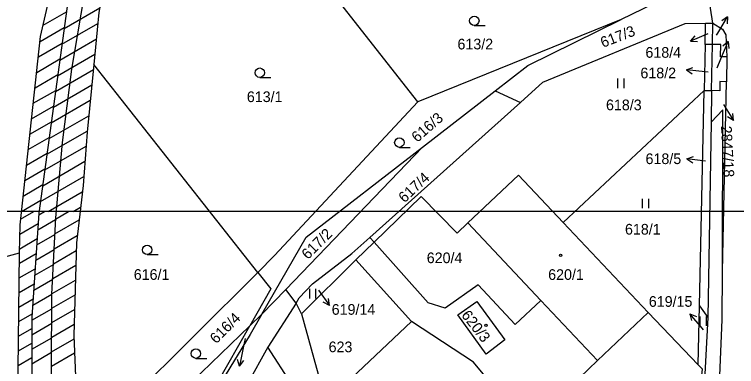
# Model space of a CAD drawing. Extents: x -558500 to -557517, y -1073973 to -1073051.
# Drawn here: x -558299.9 to -558184.7, y -1073724.7 to -1073668.6 of the extents above; entities that cross this region are included whole.
import ezdxf

# ---------------------------------------------------------------- set-up
doc = ezdxf.new("R2010")
doc.units = 0
for name, color, linetype in [('Default', 7, 'Continuous'), ('Hranice parcel', 7, 'Continuous'), ('Kolej', 7, 'Continuous'), ('Parcelní čísla', 7, 'Continuous'), ('Pop  PČ popisy', 7, 'Continuous'), ('Svazek obcí údolí Desné', 7, 'Continuous'), ('Značky budov', 7, 'Continuous'), ('Značky kultur', 7, 'Continuous')]:
    doc.layers.add(name, color=color, linetype=linetype)

msp = doc.modelspace()

# ---------------------------------------------------------------- linework, layer by layer
at = {"layer": 'Default'}
msp.add_lwpolyline([(-557909.21, -1073700), (-558500, -1073700), (-558500, -1073200), (-557800, -1073200), (-557800, -1073567.6)], dxfattribs=at)
at = {"layer": 'Hranice parcel'}
for p, q in [((-558235.56, -1073682.51), (-558250.61, -1073663.38)), ((-558188.53, -1073669.97), (-558189.35, -1073664.58)), ((-558196.23, -1073665.95), (-558203.14, -1073669.36)), ((-558203.14, -1073669.36), (-558235.56, -1073682.51)), ((-558189.77, -1073673.37), (-558189.69, -1073669.98)), ((-558189.69, -1073669.98), (-558188.53, -1073669.97)), ((-558188.59, -1073673.36), (-558188.53, -1073669.97)), ((-558188.53, -1073669.97), (-558186.98, -1073670.93)), ((-558189.77, -1073673.37), (-558189.93, -1073680.69)), ((-558188.59, -1073673.36), (-558189.77, -1073673.37)), ((-558188.72, -1073680.72), (-558188.59, -1073673.36)), ((-558187.23, -1073673.34), (-558188.59, -1073673.36)), ((-558186.31, -1073675.34), (-558186.36, -1073679.31)), ((-558261.12, -1073709.7), (-558287.25, -1073676.53)), ((-558187.01, -1073709.55), (-558186.36, -1073679.31)), ((-558234.84, -1073689.73), (-558223.26, -1073680.77)), ((-558223.26, -1073680.77), (-558219.23, -1073682.6)), ((-558189.93, -1073680.69), (-558212.4, -1073701.75)), ((-558190.64, -1073715.05), (-558189.93, -1073680.69)), ((-558189.93, -1073680.69), (-558188.72, -1073680.72)), ((-558188.72, -1073680.72), (-558188.81, -1073685.75)), ((-558187.4, -1073680.75), (-558188.72, -1073680.72)), ((-558243.24, -1073704.13), (-558219.23, -1073682.6)), ((-558186.92, -1073683.79), (-558188.81, -1073685.75)), ((-558187.01, -1073709.55), (-558186.92, -1073683.79)), ((-558188.81, -1073685.75), (-558189.35, -1073716.89)), ((-558256.63, -1073712.41), (-558234.84, -1073689.73)), ((-558227.63, -1073701.8), (-558215.96, -1073714.16)), ((-558212.4, -1073701.75), (-558198.87, -1073716.11)), ((-558242.57, -1073704.88), (-558243.24, -1073704.13)), ((-558245.46, -1073707.69), (-558242.57, -1073704.88)), ((-558233.91, -1073714.56), (-558242.57, -1073704.88)), ((-558339.57, -1073717.56), (-558299.09, -1073706.57)), ((-558245.46, -1073707.69), (-558254.11, -1073716.3)), ((-558236.6, -1073717.53), (-558245.46, -1073707.69)), ((-558256.63, -1073712.41), (-558260.45, -1073716.38)), ((-558255.01, -1073714.6), (-558256.63, -1073712.41)), ((-558255.01, -1073714.6), (-558259.48, -1073721.62)), ((-558254.11, -1073716.3), (-558255.01, -1073714.6)), ((-558206.91, -1073723.76), (-558215.96, -1073714.16)), ((-558190.86, -1073724.46), (-558190.64, -1073715.05)), ((-558190.64, -1073715.05), (-558189.35, -1073716.89)), ((-558262.39, -1073718.25), (-558260.45, -1073716.38)), ((-558254.11, -1073716.3), (-558250.26, -1073730.4)), ((-558198.87, -1073716.11), (-558206.91, -1073723.76)), ((-558190.86, -1073724.46), (-558198.87, -1073716.11)), ((-558250.26, -1073730.4), (-558236.6, -1073717.53)), ((-558226.69, -1073724.03), (-558236.6, -1073717.53)), ((-558274.72, -1073739.9), (-558262.39, -1073718.25)), ((-558259.48, -1073721.62), (-558281.15, -1073760.49)), ((-558241.29, -1073750.06), (-558259.48, -1073721.62)), ((-558218.17, -1073734.19), (-558226.69, -1073724.03))]:
    msp.add_line(p, q, dxfattribs=at)
for points in [[(-558223.26, -1073680.77), (-558218.03, -1073676.72), (-558203.14, -1073669.36)], [(-558219.23, -1073682.6), (-558215.65, -1073679.39), (-558192.95, -1073670.01), (-558189.69, -1073669.98)], [(-558186.98, -1073670.93), (-558186.43, -1073671.79), (-558186.31, -1073675.34)], [(-558186.31, -1073675.34), (-558187.29, -1073675.33), (-558187.23, -1073673.34)], [(-558186.36, -1073679.31), (-558187.4, -1073679.28), (-558187.4, -1073680.75)], [(-558235.56, -1073682.51), (-558258.46, -1073707.03), (-558261.12, -1073709.7)], [(-558260.45, -1073716.38), (-558253.37, -1073704.07), (-558234.84, -1073689.73)], [(-558227.63, -1073701.8), (-558219.54, -1073694.18), (-558212.4, -1073701.75)], [(-558242.57, -1073704.88), (-558235.04, -1073697.59), (-558229.33, -1073703.46), (-558227.63, -1073701.8)], [(-558255.01, -1073714.6), (-558254.51, -1073713.78), (-558252.39, -1073711.53), (-558246.1, -1073706.69), (-558243.24, -1073704.13)], [(-558289.37, -1073741.07), (-558281.4, -1073729.91), (-558261.12, -1073709.7)], [(-558261.12, -1073709.7), (-558259.03, -1073712.35), (-558262.39, -1073718.25)], [(-558188.37, -1073749.08), (-558187.04, -1073717.25), (-558187.01, -1073709.55)], [(-558215.96, -1073714.16), (-558220.05, -1073717.99), (-558225.94, -1073711.71), (-558231.23, -1073715.41), (-558233.91, -1073714.56)], [(-558224.7, -1073722.72), (-558229.2, -1073716.48), (-558226.19, -1073714.33), (-558221.69, -1073720.48), (-558224.7, -1073722.72)], [(-558260.45, -1073716.38), (-558262.32, -1073719.63), (-558274.72, -1073739.9)], [(-558189.35, -1073716.89), (-558191.03, -1073748.95), (-558192.59, -1073755.8)], [(-558262.39, -1073718.25), (-558277.79, -1073733.11), (-558288.61, -1073748.35)], [(-558200.5, -1073781.61), (-558202.2, -1073784.23), (-558205.35, -1073784.79), (-558212.68, -1073729.29), (-558206.91, -1073723.76)], [(-558191.18, -1073734.38), (-558190.17, -1073725.16), (-558190.86, -1073724.46)]]:
    msp.add_lwpolyline(points, dxfattribs=at)
at = {"layer": 'Kolej'}
msp.add_lwpolyline([(-558287.36, -1073784.19), (-558289.56, -1073772.87), (-558290.66, -1073766.21), (-558291.24, -1073762.21), (-558292.77, -1073749.06), (-558293.62, -1073737.47), (-558294.02, -1073725.05), (-558293.93, -1073713.18), (-558293.34, -1073701.02), (-558292.27, -1073689.01), (-558290.77, -1073677.31), (-558288.8, -1073665.65)], dxfattribs=at)
at = {"layer": 'Pop  PČ popisy'}
for p, q in [((-558187.72, -1073671.53), (-558186.17, -1073668.96)), ((-558186.17, -1073668.96), (-558187.12, -1073669.56)), ((-558186.17, -1073668.96), (-558186.26, -1073670.07)), ((-558189.32, -1073671.65), (-558192.08, -1073672.82)), ((-558192.08, -1073672.82), (-558191.36, -1073671.97)), ((-558187.93, -1073671.89), (-558187.72, -1073671.53)), ((-558192.08, -1073672.82), (-558190.96, -1073672.89)), ((-558187.24, -1073675.66), (-558186.07, -1073672.9)), ((-558186.07, -1073672.9), (-558186.92, -1073673.62)), ((-558186.07, -1073672.9), (-558186, -1073674.02)), ((-558187.86, -1073677.09), (-558187.24, -1073675.66)), ((-558192.74, -1073677.42), (-558191.7, -1073677.02)), ((-558189.76, -1073677.73), (-558192.74, -1073677.42)), ((-558192.74, -1073677.42), (-558191.8, -1073678.02)), ((-558189.29, -1073677.78), (-558189.76, -1073677.73)), ((-558186.84, -1073682.95), (-558185.25, -1073685.5)), ((-558185.25, -1073685.5), (-558185.36, -1073684.38)), ((-558185.25, -1073685.5), (-558186.2, -1073684.91)), ((-558192.66, -1073691.6), (-558191.6, -1073691.23)), ((-558189.68, -1073691.97), (-558192.66, -1073691.6)), ((-558192.66, -1073691.6), (-558191.73, -1073692.22)), ((-558251.41, -1073712.52), (-558249.69, -1073714.98)), ((-558249.69, -1073714.98), (-558250.67, -1073714.45)), ((-558249.69, -1073714.98), (-558249.85, -1073713.87)), ((-558190.25, -1073718.6), (-558192.18, -1073716.3)), ((-558192.18, -1073716.3), (-558191.15, -1073716.75)), ((-558192.18, -1073716.3), (-558191.92, -1073717.39)), ((-558190.03, -1073718.86), (-558190.25, -1073718.6)), ((-558263.11, -1073720.25), (-558263.42, -1073721.72)), ((-558263.42, -1073721.72), (-558264.04, -1073724.66)), ((-558264.04, -1073724.66), (-558264.33, -1073723.57)), ((-558264.04, -1073724.66), (-558263.35, -1073723.78))]:
    msp.add_line(p, q, dxfattribs=at)
at = {"layer": 'Svazek obcí údolí Desné'}
for p, q in [((-558295.33, -1073670.27), (-558291.64, -1073668.14)), ((-558292, -1073670.82), (-558286.3, -1073667.52)), ((-558295.83, -1073672.87), (-558291.98, -1073670.64)), ((-558292.34, -1073673.32), (-558286.61, -1073670.01)), ((-558296.1, -1073675.33), (-558292.32, -1073673.15)), ((-558292.68, -1073675.83), (-558286.85, -1073672.46)), ((-558293.03, -1073678.33), (-558287.09, -1073674.91)), ((-558296.37, -1073677.8), (-558292.66, -1073675.66)), ((-558293.37, -1073680.84), (-558287.33, -1073677.36)), ((-558296.64, -1073680.26), (-558293, -1073678.16)), ((-558293.71, -1073683.35), (-558287.58, -1073679.81)), ((-558296.91, -1073682.73), (-558293.34, -1073680.67)), ((-558294.05, -1073685.85), (-558287.82, -1073682.26)), ((-558297.18, -1073685.19), (-558293.68, -1073683.18)), ((-558297.45, -1073687.66), (-558294.02, -1073685.68)), ((-558294.39, -1073688.36), (-558288.07, -1073684.71)), ((-558294.73, -1073690.86), (-558288.31, -1073687.16)), ((-558297.72, -1073690.12), (-558294.37, -1073688.19)), ((-558295.07, -1073693.37), (-558288.5, -1073689.58)), ((-558297.99, -1073692.59), (-558294.71, -1073690.69)), ((-558295.41, -1073695.88), (-558288.69, -1073691.99)), ((-558298.26, -1073695.05), (-558295.05, -1073693.2)), ((-558295.75, -1073698.38), (-558288.87, -1073694.41)), ((-558298.53, -1073697.52), (-558295.39, -1073695.71)), ((-558294.55, -1073700), (-558289.1, -1073696.85)), ((-558298.8, -1073699.98), (-558295.73, -1073698.21)), ((-558290.55, -1073700), (-558289.38, -1073699.32)), ((-558298.93, -1073701.22), (-558296.82, -1073700)), ((-558296.03, -1073700.52), (-558295.12, -1073700)), ((-558293.35, -1073701.19), (-558291.29, -1073700)), ((-558299.05, -1073703.6), (-558296.12, -1073701.91)), ((-558296.19, -1073702.93), (-558293.36, -1073701.29)), ((-558293.47, -1073703.57), (-558289.61, -1073701.34)), ((-558296.35, -1073705.33), (-558293.47, -1073703.67)), ((-558293.58, -1073705.94), (-558289.89, -1073703.81)), ((-558299.08, -1073705.93), (-558296.28, -1073704.31)), ((-558296.51, -1073707.73), (-558293.59, -1073706.04)), ((-558293.7, -1073708.32), (-558290.06, -1073706.22)), ((-558299.11, -1073708.25), (-558296.45, -1073706.71)), ((-558296.68, -1073710.14), (-558293.7, -1073708.42)), ((-558293.81, -1073710.69), (-558290.13, -1073708.57)), ((-558299.14, -1073710.58), (-558296.61, -1073709.12)), ((-558296.84, -1073712.54), (-558293.81, -1073710.79)), ((-558293.92, -1073713.07), (-558290.19, -1073710.92)), ((-558299.17, -1073712.91), (-558296.77, -1073711.52)), ((-558297, -1073714.94), (-558293.93, -1073713.17)), ((-558293.95, -1073715.39), (-558290.26, -1073713.26)), ((-558299.2, -1073715.23), (-558296.93, -1073713.92)), ((-558297.13, -1073717.33), (-558293.95, -1073715.49)), ((-558293.97, -1073717.71), (-558290.33, -1073715.61)), ((-558299.23, -1073717.56), (-558297.1, -1073716.33)), ((-558297.14, -1073719.64), (-558293.97, -1073717.81)), ((-558293.98, -1073720.03), (-558290.39, -1073717.96)), ((-558299.26, -1073719.88), (-558297.13, -1073718.66)), ((-558297.14, -1073721.95), (-558293.98, -1073720.13)), ((-558294, -1073722.35), (-558290.42, -1073720.28)), ((-558299.29, -1073722.21), (-558297.14, -1073720.97)), ((-558297.14, -1073724.26), (-558294, -1073722.45)), ((-558294.02, -1073724.67), (-558290.33, -1073722.54)), ((-558299.31, -1073724.54), (-558297.14, -1073723.28))]:
    msp.add_line(p, q, dxfattribs=at)
for points in [[(-558237.23, -1073540.41), (-558250.35, -1073559.71), (-558264.4, -1073584.99), (-558277.08, -1073613.49), (-558283.33, -1073632.3), (-558290.3, -1073658.29), (-558296.01, -1073700.28), (-558297.13, -1073716.84), (-558297.21, -1073758.56)], [(-558299.09, -1073706.57), (-558299.03, -1073702.13), (-558295.75, -1073672.1), (-558286.79, -1073633.11)], [(-558281.64, -1073647.46), (-558284.84, -1073659.61), (-558286.44, -1073668.26), (-558287.25, -1073676.53)], [(-558287.25, -1073676.53), (-558288.33, -1073687.34), (-558288.98, -1073695.83), (-558290.03, -1073705.01), (-558290.44, -1073719.74), (-558289.69, -1073738.01), (-558289.37, -1073741.07)], [(-558298.08, -1073752.4), (-558299.44, -1073734.57), (-558299.09, -1073706.57)]]:
    msp.add_lwpolyline(points, dxfattribs=at)
at = {"layer": 'Značky budov'}
for centre in [(-558212.8, -1073706.99), (-558224.72, -1073718.13)]:
    msp.add_circle(centre, 0.175, dxfattribs=at)
at = {"layer": 'Značky kultur'}
for p, q in [((-558226.57, -1073670.32), (-558224.82, -1073670.32)), ((-558260.8, -1073678.6), (-558259.05, -1073678.6)), ((-558203.68, -1073680.3), (-558203.68, -1073678.8)), ((-558202.68, -1073680.3), (-558202.68, -1073678.8)), ((-558238.53, -1073689.76), (-558236.78, -1073689.76)), ((-558199.75, -1073699.45), (-558199.75, -1073697.95)), ((-558198.75, -1073699.45), (-558198.75, -1073697.95)), ((-558278.75, -1073706.87), (-558277, -1073706.87)), ((-558252.83, -1073713.85), (-558252.83, -1073712.35)), ((-558251.83, -1073713.85), (-558251.83, -1073712.35)), ((-558190.54, -1073718.24), (-558190.54, -1073716.74)), ((-558189.54, -1073718.24), (-558189.54, -1073716.74)), ((-558270.97, -1073723.41), (-558269.22, -1073723.41))]:
    msp.add_line(p, q, dxfattribs=at)
for centre in [(-558226.57, -1073669.57), (-558260.8, -1073677.85), (-558238.53, -1073689.01), (-558278.75, -1073706.12), (-558270.97, -1073722.66)]:
    msp.add_circle(centre, 0.75, dxfattribs=at)

# ---------------------------------------------------------------- texts
at = {"layer": 'Parcelní čísla'}
for s, rotation, p in [('617/3', 21, (-558206.06, -1073673.9)), ('616/3', 41, (-558235.68, -1073689.06)), ('2847/18', 273, (-558187.23, -1073686.37)), ('617/4', 43, (-558237.71, -1073698.7)), ('617/2', 45, (-558253.11, -1073707.74)), ('616/4', 45, (-558267.74, -1073721.18)), ('620/3', 308, (-558228.73, -1073716.55))]:
    msp.add_text(s, height=1.7, rotation=rotation, dxfattribs=at).set_placement(p)
for s, p in [('613/2', (-558229.26, -1073674.14)), ('618/4', (-558199.28, -1073675.47)), ('618/2', (-558200.08, -1073678.75)), ('613/1', (-558262.85, -1073682.54)), ('618/3', (-558205.57, -1073683.84)), ('618/5', (-558199.26, -1073692.43)), ('618/1', (-558202.54, -1073703.67)), ('620/4', (-558234.16, -1073708.23)), ('616/1', (-558280.89, -1073710.89)), ('620/1', (-558214.79, -1073710.9)), ('619/15', (-558198.74, -1073715.19)), ('619/14', (-558249.32, -1073716.46)), ('623', (-558249.81, -1073722.43))]:
    msp.add_text(s, height=1.7, dxfattribs=at).set_placement(p)

doc.saveas('drawing.dxf')
